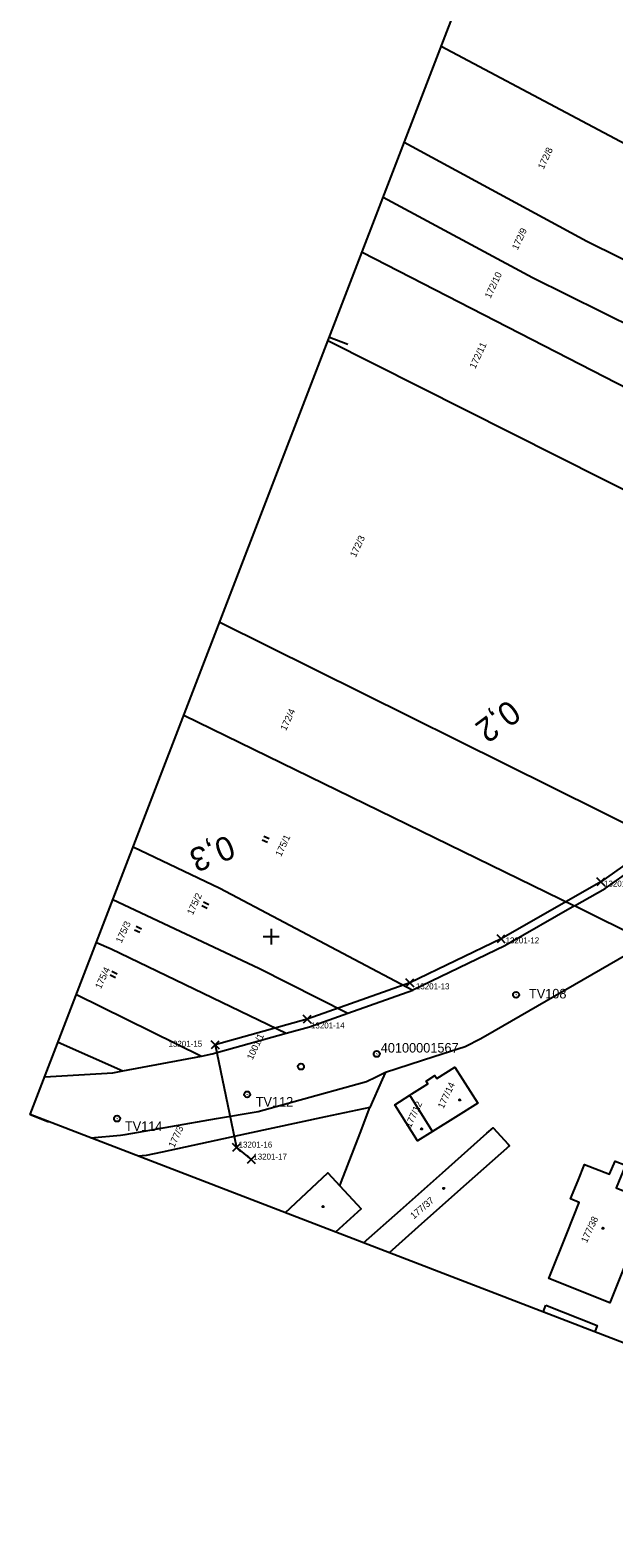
# Model space of a CAD drawing. Extents: x -755061 to -754557, y -1162352 to -1161657.
# Drawn here: x -755060.7 to -754913.6, y -1162351.5 to -1161971.5 of the extents above; entities that cross this region are included whole.
import ezdxf

# ---------------------------------------------------------------- set-up
doc = ezdxf.new("R2010")
doc.units = 0
for name, color, linetype in [('Body ŽBP', 7, 'Continuous'), ('Formát', 7, 'Continuous'), ('SO_01_32_01', 7, 'Continuous'), ('Staniceni a namezniky', 7, 'Continuous'), ('Síť', 7, 'Continuous'), ('VB_01_32_01', 7, 'Continuous'), ('Vrstva 55', 7, 'Continuous'), ('Vrstva 57', 7, 'Continuous'), ('Vrstva 58', 7, 'Continuous'), ('Vrstva 59', 7, 'Continuous')]:
    doc.layers.add(name, color=color, linetype=linetype)

msp = doc.modelspace()

# ---------------------------------------------------------------- linework, layer by layer
at = {"layer": 'Body ŽBP'}
for p, q in [((-754938.24, -1162214.59), (-754938.28, -1162214.69)), ((-754938.26, -1162214.64), (-754938.26, -1162214.64)), ((-754973.58, -1162229.89), (-754973.58, -1162229.89)), ((-754973.37, -1162229.51), (-754973.41, -1162229.6)), ((-754973.39, -1162229.56), (-754973.39, -1162229.56)), ((-755006.03, -1162239.68), (-755006.07, -1162239.78)), ((-755006.05, -1162239.73), (-755006.05, -1162239.73)), ((-755038.82, -1162245.81), (-755038.86, -1162245.91)), ((-755038.84, -1162245.86), (-755038.84, -1162245.86))]:
    msp.add_line(p, q, dxfattribs=at)
for centre in [(-754938.26, -1162214.64), (-754973.39, -1162229.56), (-755006.05, -1162239.73), (-755038.84, -1162245.86)]:
    msp.add_circle(centre, 0.756, dxfattribs=at)
at = {"layer": 'Formát'}
for p, q in [((-754985.32, -1162048.86), (-754980.65, -1162050.65)), ((-755060.75, -1162244.84), (-755056.08, -1162246.64))]:
    msp.add_line(p, q, dxfattribs=at)
msp.add_lwpolyline([(-754909.9, -1161852.87), (-754632.71, -1161959.54), (-754783.57, -1162351.52), (-755060.75, -1162244.84)], close=True, dxfattribs=at)
at = {"layer": 'SO_01_32_01'}
msp.add_lwpolyline([(-754758.34, -1161933.06), (-754762.34, -1161937.68), (-754763.29, -1161936.85), (-754776.47, -1161949.62), (-754777.37, -1161978.41), (-754796.3, -1162026.28), (-754809.87, -1162057.58), (-754831.07, -1162091.65), (-754857.54, -1162133.93), (-754885.68, -1162161.18), (-754896.77, -1162171.93), (-754916.86, -1162186.18), (-754942.05, -1162200.54), (-754965.03, -1162211.64), (-754990.89, -1162220.78), (-755014.11, -1162227.27), (-755008.76, -1162253.14), (-755005.05, -1162256.17)], dxfattribs=at)
at = {"layer": 'Staniceni a namezniky'}
msp.add_circle((-754992.48, -1162232.74), 0.75, dxfattribs=at)
at = {"layer": 'Síť'}
for points in [[(-754998, -1162200), (-755000, -1162200), (-755002, -1162200)], [(-755000, -1162198), (-755000, -1162200), (-755000, -1162202)]]:
    msp.add_lwpolyline(points, dxfattribs=at)
at = {"layer": 'VB_01_32_01'}
for p, q in [((-754916.86, -1162186.18), (-754917.86, -1162185.18)), ((-754916.86, -1162186.18), (-754915.86, -1162185.18)), ((-754916.86, -1162186.18), (-754917.86, -1162187.18)), ((-754916.86, -1162186.18), (-754915.86, -1162187.18)), ((-754942.05, -1162200.54), (-754943.05, -1162199.54)), ((-754942.05, -1162200.54), (-754943.05, -1162201.54)), ((-754942.05, -1162200.54), (-754941.05, -1162199.54)), ((-754942.05, -1162200.54), (-754941.05, -1162201.54)), ((-754965.03, -1162211.64), (-754966.03, -1162210.64)), ((-754965.03, -1162211.64), (-754966.03, -1162212.64)), ((-754965.03, -1162211.64), (-754964.03, -1162210.64)), ((-754965.03, -1162211.64), (-754964.03, -1162212.64)), ((-754990.89, -1162220.78), (-754991.89, -1162219.78)), ((-754990.89, -1162220.78), (-754989.89, -1162219.78)), ((-754990.89, -1162220.78), (-754991.89, -1162221.78)), ((-754990.89, -1162220.78), (-754989.89, -1162221.78)), ((-755014.11, -1162227.27), (-755015.11, -1162226.27)), ((-755014.11, -1162227.27), (-755015.11, -1162228.27)), ((-755014.11, -1162227.27), (-755013.11, -1162226.27)), ((-755014.11, -1162227.27), (-755013.11, -1162228.27)), ((-755008.76, -1162253.14), (-755009.76, -1162252.14)), ((-755008.76, -1162253.14), (-755009.76, -1162254.14)), ((-755008.76, -1162253.14), (-755007.76, -1162252.14)), ((-755008.76, -1162253.14), (-755007.76, -1162254.14)), ((-755005.05, -1162256.17), (-755006.05, -1162255.17)), ((-755005.05, -1162256.17), (-755006.05, -1162257.17)), ((-755005.05, -1162256.17), (-755004.05, -1162255.17)), ((-755005.05, -1162256.17), (-755004.05, -1162257.17))]:
    msp.add_line(p, q, dxfattribs=at)
at = {"layer": 'Vrstva 55'}
for p, q in [((-755012.97, -1162120.69), (-754900.06, -1162176.77)), ((-755021.99, -1162144.14), (-754923.5, -1162192.2)), ((-754905.78, -1162201), (-754923.5, -1162192.2)), ((-754980.63, -1162219.28), (-754964.26, -1162213.49)), ((-755037.41, -1162233.8), (-755017.58, -1162230.07)), ((-754959.28, -1162249.1), (-754965.02, -1162239.9))]:
    msp.add_line(p, q, dxfattribs=at)
for points in [[(-754957.1, -1161975.52), (-754888.73, -1162011.84), (-754815.21, -1162048.8)], [(-754966.42, -1161999.75), (-754920.4, -1162024.65), (-754828.75, -1162070.02)], [(-754971.75, -1162013.61), (-754934.11, -1162033.82), (-754837.06, -1162081.94)], [(-754977.09, -1162027.47), (-754900.68, -1162066.68), (-754845.66, -1162094.27)], [(-754858.37, -1162113.93), (-754985.69, -1162049.81)], [(-755034.76, -1162177.32), (-755012.93, -1162187.79), (-754964.26, -1162213.49)], [(-754923.5, -1162192.2), (-754915.78, -1162187.87), (-754900.06, -1162176.77)], [(-755039.87, -1162190.6), (-755003.14, -1162207.94), (-754980.63, -1162219.28)], [(-754923.5, -1162192.2), (-754941.12, -1162202.31), (-754964.26, -1162213.49)], [(-754971.15, -1162234.1), (-754958.95, -1162230.19), (-754951.07, -1162227.67), (-754947.14, -1162225.65), (-754943.74, -1162223.69), (-754908.27, -1162203.24), (-754905.78, -1162201)], [(-755044.04, -1162201.44), (-755040.35, -1162203.08), (-754996.22, -1162224.35)], [(-755049.1, -1162214.57), (-755017.58, -1162230.07)], [(-754996.22, -1162224.35), (-754990.29, -1162222.69), (-754980.63, -1162219.28)], [(-755053.71, -1162226.55), (-755037.41, -1162233.8)], [(-755017.58, -1162230.07), (-755014.83, -1162229.55), (-754996.22, -1162224.35)], [(-755057.07, -1162235.3), (-755039.91, -1162234.27), (-755037.41, -1162233.8)], [(-755045.47, -1162250.72), (-755038.01, -1162250.05), (-755036.82, -1162249.84), (-755013.79, -1162245.86), (-755003.23, -1162244.03), (-754994.22, -1162241.55), (-754975.93, -1162236.51), (-754973.51, -1162235.29), (-754971.15, -1162234.1)], [(-754971.15, -1162234.1), (-754972, -1162236.02), (-754975.1, -1162243.04)], [(-754965.02, -1162239.9), (-754964.51, -1162239.63), (-754960.48, -1162237.12), (-754960.95, -1162236.39), (-754958.69, -1162234.97), (-754958.23, -1162235.71), (-754953.68, -1162232.85), (-754947.93, -1162241.97), (-754953.52, -1162245.48), (-754959.28, -1162249.1)], [(-754959.28, -1162249.1), (-754963.09, -1162251.49), (-754968.85, -1162242.38), (-754965.02, -1162239.9)], [(-754975.1, -1162243.04), (-754986.3, -1162245.44), (-755006.22, -1162249.72), (-755027.5, -1162254.28), (-755031.53, -1162255.15), (-755033.53, -1162255.32)], [(-754982.72, -1162262.75), (-754982.38, -1162261.87), (-754977.59, -1162249.49), (-754975.1, -1162243.04)], [(-754956.8, -1162259.49), (-754945.64, -1162249.55), (-754944.05, -1162248.14), (-754940.25, -1162252.33), (-754939.94, -1162252.67), (-754950.82, -1162262.37), (-754961.31, -1162271.72), (-754970.23, -1162279.68)], [(-754922.63, -1162261.43), (-754921.01, -1162257.39), (-754914.72, -1162259.89), (-754913.29, -1162256.54), (-754910.69, -1162257.6), (-754913.05, -1162263.33), (-754904.47, -1162266.73), (-754905.81, -1162270.11), (-754910.45, -1162281.8), (-754914.62, -1162292.29), (-754930, -1162286.19), (-754925.41, -1162274.6), (-754922.38, -1162266.96), (-754924.5, -1162266.11), (-754922.63, -1162261.43)], [(-754996.49, -1162269.58), (-754985.67, -1162259.55), (-754982.72, -1162262.75)], [(-754976.68, -1162277.2), (-754967.36, -1162268.89), (-754956.8, -1162259.49)], [(-754982.72, -1162262.75), (-754977.34, -1162268.59), (-754983.75, -1162274.48)], [(-754931.45, -1162294.6), (-754930.78, -1162292.9)], [(-754930.78, -1162292.9), (-754917.8, -1162298.01), (-754918.43, -1162299.61)]]:
    msp.add_lwpolyline(points, dxfattribs=at)
at = {"layer": 'Vrstva 58'}
for p, q in [((-755000.92, -1162176.26), (-755002.28, -1162175.63)), ((-755000.5, -1162175.35), (-755001.86, -1162174.72)), ((-755016.1, -1162192.86), (-755017.46, -1162192.23)), ((-755015.67, -1162191.96), (-755017.03, -1162191.32)), ((-755033.1, -1162198.97), (-755034.46, -1162198.34)), ((-755032.67, -1162198.07), (-755034.03, -1162197.43)), ((-755039.22, -1162210.35), (-755040.58, -1162209.72)), ((-755038.79, -1162209.45), (-755040.15, -1162208.81))]:
    msp.add_line(p, q, dxfattribs=at)
at = {"layer": 'Vrstva 59'}
for centre in [(-754952.44, -1162241.15), (-754962.08, -1162248.45), (-754956.47, -1162263.43), (-754986.89, -1162268.03), (-754916.37, -1162273.47)]:
    msp.add_circle(centre, 0.175, dxfattribs=at)

# ---------------------------------------------------------------- texts
at = {"layer": 'Body ŽBP'}
for s, p in [(' TV108', (-754935.89, -1162215.55)), (' 40100001567', (-754973.26, -1162229.2)), (' TV112', (-755004.78, -1162242.81)), (' TV114', (-755037.75, -1162248.95))]:
    msp.add_text(s, height=2.4, dxfattribs=at).set_placement(p)
at = {"layer": 'Staniceni a namezniky'}
for s, rotation, p in [('0,2', 216.7166, (-754940.07, -1162139.99)), ('0,3', 201.4151, (-755010.69, -1162174.24))]:
    msp.add_text(s, height=6, rotation=rotation, dxfattribs=at).set_placement(p)
at = {"layer": 'VB_01_32_01'}
for s, p in [(' 13201-11', (-754916.64, -1162187.36)), (' 13201-12', (-754941.46, -1162201.68)), (' 13201-13', (-754964.07, -1162213.26)), (' 13201-14', (-754990.51, -1162223.12)), (' 13201-15', (-755026.42, -1162227.74)), (' 13201-16', (-755008.76, -1162253.14)), (' 13201-17', (-755005.05, -1162256.17))]:
    msp.add_text(s, height=1.5, dxfattribs=at).set_placement(p)
at = {"layer": 'Vrstva 57'}
for s, rotation, p in [('172/8', 65, (-754931.32, -1162006.71)), ('172/9', 65, (-754937.86, -1162027.04)), ('172/10', 65, (-754944.7, -1162039.26)), ('172/11', 65, (-754948.55, -1162056.98)), ('172/3', 65, (-754978.68, -1162104.52)), ('172/4', 65, (-754996.26, -1162148.21)), ('175/1', 65, (-754997.49, -1162179.94)), ('175/2', 65, (-755019.76, -1162194.66)), ('175/3', 65, (-755037.72, -1162201.74)), ('175/4', 65, (-755042.93, -1162213.32)), ('1001/1', 65, (-755004.68, -1162231.19)), ('177/14', 65, (-754956.55, -1162243.48)), ('177/12', 65, (-754964.8, -1162248.3)), ('177/3', 65, (-755024.43, -1162253.32)), ('177/37', 40.664, (-754964.03, -1162271.28)), ('177/38', 65, (-754920.43, -1162277.31))]:
    msp.add_text(s, height=1.7, rotation=rotation, dxfattribs=at).set_placement(p)

doc.saveas('drawing.dxf')
